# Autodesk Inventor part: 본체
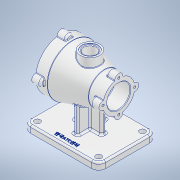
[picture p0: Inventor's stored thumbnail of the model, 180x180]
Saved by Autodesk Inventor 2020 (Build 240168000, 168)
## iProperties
Created: 2020-12
Part Number: 본체
Material: 알루미늄 6061
Document SubType Name: Modeling
Designer: USER
Density: 2.7 g/cm^3
Appearance: 알루미늄 - 평지
Mass: 1083.15 g
Surface Area: 851.644 cm^2
Volume: 401.166 cm^3
Author: USER
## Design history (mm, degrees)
sketch "스케치1"
  geometry: L1 (65, -50)-(-65, -50); L2 (-65, -50)-(-65, 50); L3 (-65, 50)-(65, 50); L4 (65, 50)-(65, -50); 1 further point
  constraints: 8 end point, 2 parallel, 1 horizontal, 1 perpendicular
  dimensions: "d0" = 100 distance of L1.end L2.end; "d1" = 130 distance of L1.start L1.end; "d2" = 50 distance from line of L1 point (0, 0); "d3" = 65 distance from line of L2 point (0, 0)
extrude "돌출1" new body sketch "스케치1" distance "d4" = 12; taper "d5" = 0 deg
fillet "모깎기1" dims "d6" = 12
sketch "스케치3"
  geometry: L1 (-50, 126)-(-30, 126); L2 (-30, 126)-(25, 109.5); L3 (25, 109.5)-(50, 109.5); L4 (65, 0)-(53, 0) reference; L5 (-53, 0)-(53, 0) reference; L6 (-50, 82)-(77.95, 82); L7 (-50, 126)-(-50, 114); L8 (-50, 114)-(-27, 114); L9 (-27, 114)-(-27, 108); L10 (-27, 108)-(20, 108); L11 (20, 108)-(20, 102); L12 (20, 102)-(50, 102); L13 (50, 102)-(50, 109.5); L14 (0, 0)-(-50, 0); 3 further points
  constraints: 24 end point, 5 perpendicular, 2 horizontal, 2 midpoint, 2 vertical, 2 vertical alignment, 1 parallel
  dimensions: "d17" = 25 distance of L2.end L3.end; "d22" = 64 diameter of L8 L6; "d23" = 52 diameter of L10 L6; "d24" = 88 diameter of L1 L6; "d25" = 55 diameter of L3 L6; "d26" = 82 distance from line of L4 L6.end; "d27" = 40 diameter of L12 L6; "d28" = 20 distance from line of L1.end L7; "d29" = 23 distance between parallel lines of L7 L9; "d30" = 47 distance between parallel lines of L11 L9; "d31" = 30 distance between parallel lines of L13 L11; "d32" = 50 distance of L14.start L14.end
revolve "회전2" sketch "스케치3" stored, may be unused: angle "d20" = 90 deg
fillet "모깎기2" dims "d33" = 3
fillet "모깎기3" dims "d34" = 3
fillet "모깎기4" dims "d35" = 3
chamfer "모따기1" distance "d36" = 1; stored, may be unused: second distance "d37" = 2, angle "d38" = 45 deg
chamfer "모따기2" distance "d39" = 1; stored, may be unused: second distance "d40" = 2, angle "d41" = 45 deg
sketch "스케치4"
  geometry: L1 (0, 0)-(0, 44); C1 r 7 at (0, 44); 3 further points
  constraints: 2 end point, 1 centre point, 1 coincident, 1 vertical, 2 other
  dimensions: "d42" = 14 diameter of C1
extrude "돌출2" join sketch "스케치4" distance "d43" = 15; taper "d44" = 0 deg
sketch "스케치5"
  geometry: L1 (0, 0)-(0, 27.5); C1 r 7 at (0, 27.5); 3 further points
  constraints: 2 end point, 1 centre point, 1 coincident, 1 vertical, 2 other
  dimensions: "d48" = 14 diameter of C1
extrude "돌출3" join sketch "스케치5" distance "d49" = 15; taper "d50" = 0 deg
sketch "스케치6"
  geometry: A1 r 7 centre (0, 0) between (6.978, -0.557) and (-6.978, -0.557) reference; 2 further points
  constraints: 1 coincident
hole "구멍1" sketch "스케치6" at (0, 0) diameter "d54" = 4.134; stored, may be unused: countersink angle "d58" = 90 deg, drill point angle "d60" = 118 deg; dims "d55" = 9, "d56" = 4, "d57" = 2, "d59" = 11
sketch "스케치7"
  geometry: A1 r 7 centre (0, 0) between (6.943, -0.891) and (-6.943, -0.891) reference; 2 further points
  constraints: 1 coincident
hole "구멍2" sketch "스케치7" at (0, 0) diameter "d64" = 4.134; stored, may be unused: countersink angle "d68" = 90 deg, drill point angle "d70" = 118 deg; dims "d65" = 9, "d66" = 4, "d67" = 2, "d69" = 11
node "작업 평면1"
sketch "스케치8"
  geometry: C1 r 17 at (-3.5, 0); 1 further point
  constraints: 1 centre point, 1 coincident
  dimensions: "d74" = 34 diameter of C1
extrude "돌출4" join sketch "스케치8" distance "d75" = 19; taper "d76" = 0 deg
sketch "스케치9"
  geometry: C1 r 14 at (0, 0); 1 further point
  constraints: 1 centre point, 1 coincident
  dimensions: "d77" = 28 diameter of C1
extrude "돌출5" cut sketch "스케치9" distance "d78" = 1; taper "d79" = 0 deg
sketch "스케치10"
  geometry: C1 r 11 at (0, 0); 1 further point
  constraints: 1 centre point, 1 coincident
  dimensions: "d80" = 22 diameter of C1
extrude "돌출6" cut sketch "스케치10" distance "d81" = 25; taper "d82" = 0 deg
chamfer "모따기3" distance "d83" = 1; stored, may be unused: second distance "d84" = 2, angle "d85" = 45 deg
sketch "스케치12"
  geometry: L1 (4, -25)-(-4, -25); L2 (-4, -25)-(-4, 25); L3 (-4, 25)-(4, 25); L4 (4, 25)-(4, -25); 1 further point
  constraints: 8 end point, 2 parallel, 1 horizontal, 1 perpendicular
  dimensions: "d90" = 8 distance of L1.start L1.end; "d91" = 50 distance of L3.end L1.start; "d92" = 25 distance from line of L1 point (0, 0); "d93" = 4 distance from line of L4 point (0, 0)
extrude "돌출7" join sketch "스케치12" stored distance "d94" = 25; taper "d95" = 0 deg
sketch "스케치13"
  geometry: L1 (-24, 4)-(24, 4); L2 (24, 4)-(24, -4); L3 (24, -4)-(-24, -4); L4 (-24, -4)-(-24, 4); 1 further point
  constraints: 8 end point, 2 parallel, 1 horizontal, 1 perpendicular
  dimensions: "d96" = 8 distance of L1.end L2.end; "d97" = 48 distance of L1.start L1.end; "d98" = 24 distance from line of L4 point (0, 0); "d99" = 4 distance from line of L1 point (0, 0)
extrude "돌출8" join sketch "스케치13" stored distance "d100" = 25; taper "d101" = 0 deg
fillet "모깎기5" dims "d102" = 3
fillet "모깎기6" dims "d103" = 3
fillet "모깎기7" dims "d104" = 3
sketch "스케치17"
  geometry: L1 (-53, -50)-(53, -50) reference; 2 further points
  constraints: 1 vertical alignment, 1 other
  dimensions: "d105" = 10 distance from line of L1 point (0, -40)
feature "엠보싱1" sketch "스케치17" dims "d106" = 0.5, "d107" = 0
fillet "모깎기8" dims "d108" = 1
fillet "모깎기9" dims "d109" = 3
fillet "모깎기10" dims "d110" = 1
fillet "모깎기11" dims "d111" = 3
fillet "모깎기12" dims "d112" = 3
sketch "스케치18"
  geometry: C1 r 5 at (-53, 38); C2 r 5 at (53, 38); C3 r 5 at (53, -38); C4 r 5 at (-53, -38); A1 r 12 centre (-53, 38) between (-53, 50) and (-65, 38) reference; A2 r 12 centre (53, 38) between (65, 38) and (53, 50) reference; A3 r 12 centre (53, -38) between (53, -50) and (65, -38) reference; A4 r 12 centre (-53, -38) between (-65, -38) and (-53, -50) reference; 1 further point
  constraints: 4 centre point, 4 coincident
  dimensions: "d113" = 10 diameter of C1; "d114" = 10 diameter of C2; "d115" = 10 diameter of C3; "d116" = 10 diameter of C4
extrude "돌출9" cut sketch "스케치18" distance "d117" = 25; taper "d118" = 0 deg
node "솔리드1"
pattern_circular "원형 패턴1" dims angle "d46" = 360 deg
pattern_circular "원형 패턴2" dims angle "d52" = 360 deg
pattern_circular "원형 패턴3" dims angle "d62" = 360 deg
pattern_circular "원형 패턴4" dims angle "d72" = 360 deg
feature "A9D066F2-1C7D-4E18-AEED-F7BC21143FA4" dims "d64" = 4.134, "d65" = 9, "d66" = 4, "d67" = 2, "d68" = 90 deg, "d69" = 11, "d70" = 118 deg
